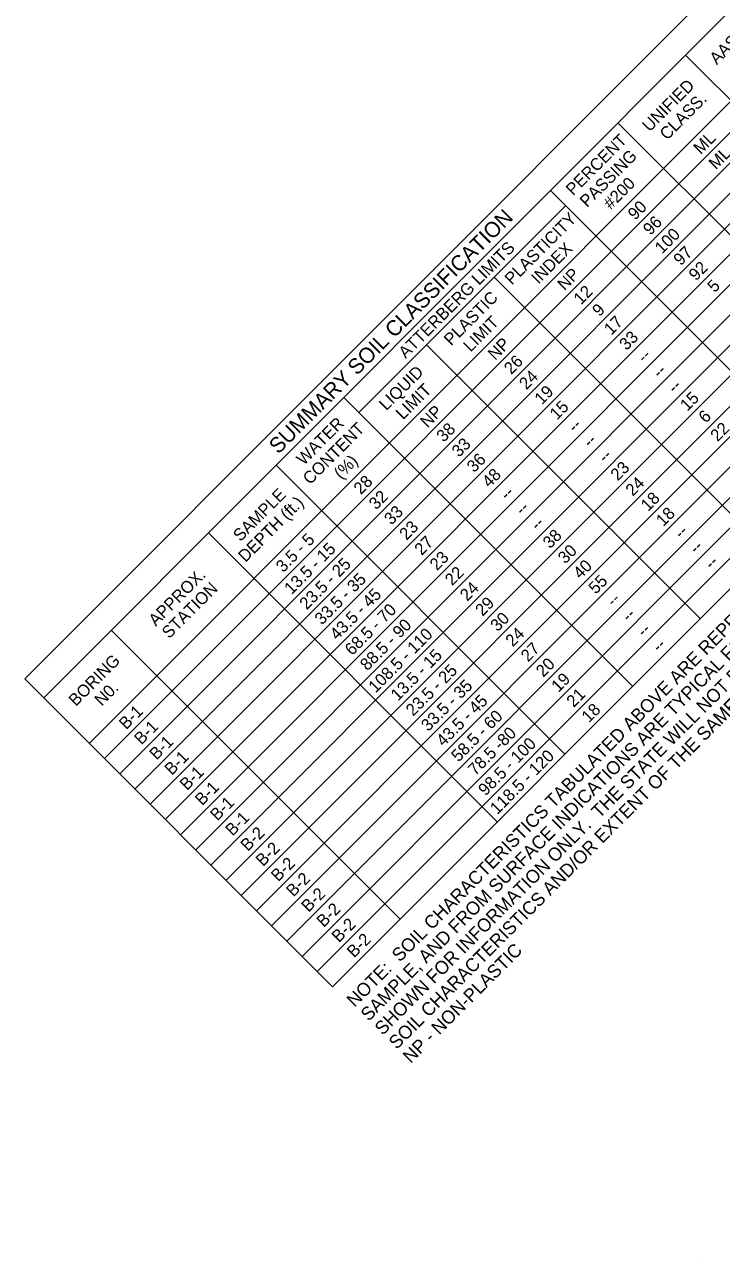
# Model space of a CAD drawing. Extents: x 1675667 to 1681231, y 227227 to 232694.
# Drawn here: x 1678206 to 1678522, y 230060 to 230621 of the extents above; entities that cross this region are included whole.
import ezdxf

# ---------------------------------------------------------------- set-up
doc = ezdxf.new("R2010")
doc.units = 0
doc.layers.add('Default', color=7, linetype='Continuous')
doc.layers.add('R_Annotation', color=7, linetype='Continuous')

msp = doc.modelspace()

# ---------------------------------------------------------------- linework, layer by layer
at = {"layer": 'Default'}
for p, q in [((1678205.92, 230324.54), (1678527.85, 230646.54)), ((1678214.54, 230315.92), (1678536.47, 230637.93)), ((1678235.23, 230295.24), (1678557.15, 230617.25)), ((1678465.12, 230525.19), (1678557.15, 230617.25)), ((1678242.12, 230288.35), (1678564.05, 230610.35)), ((1678636.8, 230476.27), (1678505.79, 230607.24)), ((1678249.02, 230281.46), (1678570.94, 230603.46)), ((1678255.91, 230274.56), (1678577.84, 230596.56)), ((1678262.81, 230267.67), (1678584.73, 230589.67)), ((1678269.7, 230260.77), (1678591.63, 230582.78)), ((1678276.6, 230253.88), (1678598.52, 230575.88)), ((1678606.12, 230445.58), (1678475.11, 230576.56)), ((1678283.49, 230246.99), (1678605.42, 230568.99)), ((1678290.39, 230240.09), (1678612.31, 230562.1)), ((1678297.28, 230233.2), (1678619.21, 230555.2)), ((1678304.18, 230226.31), (1678626.1, 230548.31)), ((1678575.45, 230414.9), (1678444.44, 230545.88)), ((1678311.07, 230219.41), (1678633, 230541.42)), ((1678357.58, 230445.21), (1678451.33, 230538.98)), ((1678317.97, 230212.52), (1678639.89, 230534.52)), ((1678324.86, 230205.63), (1678646.79, 230527.63)), ((1678331.76, 230198.73), (1678653.68, 230520.74)), ((1678338.65, 230191.84), (1678660.58, 230513.84)), ((1678345.55, 230184.95), (1678667.47, 230506.95)), ((1678543.05, 230382.49), (1678418.93, 230506.57)), ((1678512.37, 230351.81), (1678388.26, 230475.89)), ((1678481.69, 230321.13), (1678350.69, 230452.1)), ((1678451.02, 230290.44), (1678320.01, 230421.42)), ((1678420.34, 230259.76), (1678289.34, 230390.73)), ((1678376.22, 230215.63), (1678245.22, 230346.61)), ((1678345.55, 230184.95), (1678205.92, 230324.54)), ((1678511.22, 230060.07), (1678511.22, 230060.07))]:
    msp.add_line(p, q, dxfattribs=at)
at = {"layer": 'R_Annotation'}
msp.add_line((1678205.92, 230324.54), (1678205.92, 230324.54), dxfattribs=at)

# ---------------------------------------------------------------- texts
at = {"layer": 'Default'}
for s, height, p in [('AASHTO', 5.5, (1678519.93, 230602.65)), ('UNIFIED', 5.5, (1678489.45, 230572.16)), ('CLASS.', 5.5, (1678497.36, 230568.4)), ('PERCENT', 5.5, (1678454.75, 230543.28)), ('ML', 5.5, (1678512.65, 230561.95)), ('PASSING', 5.5, (1678461.08, 230537.95)), ('ML', 5.5, (1678519.54, 230555.05)), ('#200', 5.5, (1678471.8, 230537)), ('90', 5.5, (1678482.86, 230532.15)), ('SUMMARY SOIL CLASSIFICATION', 7, (1678320.99, 230426.07)), ('PLASTICITY', 5.5, (1678426.97, 230502.77)), ('96', 5.5, (1678489.77, 230525.27)), ('100', 5.5, (1678495.09, 230516.81)), ('ATTERBERG LIMITS', 5.5, (1678378.78, 230469.42)), ('INDEX', 5.5, (1678439, 230503.13)), ('97', 5.5, (1678503.58, 230511.5)), ('NP', 5.5, (1678450.89, 230500.18)), ('92', 5.5, (1678510.5, 230504.64)), ('5', 5.5, (1678518.96, 230499.31)), ('PLASTIC', 5.5, (1678399.4, 230475.2)), ('12', 5.5, (1678458.28, 230493.77)), ('9', 5.5, (1678466.71, 230488.42)), ('LIMIT', 5.5, (1678408.25, 230472.37)), ('17', 5.5, (1678472.04, 230479.96)), ('NP', 5.5, (1678419.36, 230468.63)), ('33', 5.5, (1678478.98, 230473.11)), ('26', 5.5, (1678426.69, 230462.18)), ('--', 5.5, (1678487.02, 230467.36)), ('LIQUID', 5.5, (1678369.99, 230445.78)), ('--', 5.5, (1678493.91, 230460.46)), ('NOTE:  SOIL CHARACTERISTICS TABULATED ABOVE ARE REPRESENTATIVE AT THE LOCATION OF THE', 6, (1678355.62, 230175.36)), ('24', 5.5, (1678433.55, 230455.25)), ('SAMPLE, AND FROM SURFACE INDICATIONS ARE TYPICAL FOR THE LIMITS SHOWN.  THESE DATA ARE ', 6, (1678361.99, 230169)), ('LIMIT', 5.5, (1678377.57, 230441.69)), ('19', 5.5, (1678440.52, 230448.43)), ('--', 5.5, (1678500.81, 230453.57)), ('15', 5.5, (1678506.55, 230445.53)), ('15', 5.5, (1678447.43, 230441.56)), ('SHOWN FOR INFORMATION ONLY.  THE STATE WILL NOT BE RESPONSIBLE FOR VARIATIONS IN THE ', 6, (1678368.35, 230162.64)), ('NP', 5.5, (1678388.68, 230437.95)), ('6', 5.5, (1678514.94, 230440.13)), ('WATER', 5.5, (1678332.51, 230421.01)), ('CONTENT', 5.5, (1678335.4, 230412.23)), ('SOIL CHARACTERISTICS AND/OR EXTENT OF THE SAME DIFFERING FROM THE ABOVE TABULATIONS.', 6, (1678374.72, 230156.27)), ('38', 5.5, (1678396.02, 230431.5)), ('--', 5.5, (1678455.48, 230435.81)), ('22', 5.5, (1678520.33, 230431.73)), ('33', 5.5, (1678402.98, 230424.67)), ('--', 5.5, (1678462.37, 230428.92)), ('36', 5.5, (1678409.81, 230417.71)), ('--', 5.5, (1678469.27, 230422.03)), ('(%)', 5.5, (1678349.49, 230414.66)), ('23', 5.5, (1678475.02, 230413.99)), ('28', 5.5, (1678358.45, 230407.71)), ('48', 5.5, (1678416.71, 230410.82)), ('24', 5.5, (1678481.82, 230407)), ('SAMPLE', 5.5, (1678303.78, 230386.44)), ('32', 5.5, (1678365.39, 230400.86)), ('--', 5.5, (1678424.8, 230405.13)), ('DEPTH (ft.)', 5.5, (1678306.08, 230377.07)), ('18', 5.5, (1678488.75, 230400.14)), ('33', 5.5, (1678372.3, 230393.98)), ('--', 5.5, (1678431.7, 230398.24)), ('18', 5.5, (1678495.65, 230393.25)), ('23', 5.5, (1678379.19, 230387.09)), ('--', 5.5, (1678438.59, 230391.34)), ('--', 5.5, (1678503.75, 230387.56)), ('3.5 - 5', 5.5, (1678323.18, 230372.43)), ('27', 5.5, (1678386.04, 230380.15)), ('38', 5.5, (1678444.29, 230383.25)), ('13.5 - 15', 5.5, (1678326.97, 230362.43)), ('23', 5.5, (1678392.99, 230373.3)), ('30', 5.5, (1678451.16, 230376.33)), ('--', 5.5, (1678510.64, 230380.67)), ('23.5 - 25', 5.5, (1678333.87, 230355.54)), ('40', 5.5, (1678458.06, 230369.44)), ('--', 5.5, (1678517.54, 230373.77)), ('APPROX.', 5.5, (1678265.41, 230348.07)), ('33.5 - 35', 5.5, (1678340.76, 230348.65)), ('22', 5.5, (1678399.86, 230366.39)), ('55', 5.5, (1678465.02, 230362.62)), ('STATION', 5.5, (1678271.45, 230342.43)), ('43.5 - 45', 5.5, (1678347.66, 230341.75)), ('24', 5.5, (1678406.68, 230359.42)), ('29', 5.5, (1678413.64, 230352.59)), ('--', 5.5, (1678473.07, 230356.88)), ('68.5 - 70', 5.5, (1678354.48, 230334.79)), ('30', 5.5, (1678420.49, 230345.65)), ('--', 5.5, (1678479.97, 230349.98)), ('88.5 - 90', 5.5, (1678361.37, 230327.89)), ('24', 5.5, (1678427.36, 230338.74)), ('--', 5.5, (1678486.86, 230343.09)), ('108.5 - 110', 5.5, (1678365.16, 230317.89)), ('13.5 - 15', 5.5, (1678375.24, 230314.18)), ('27', 5.5, (1678434.31, 230331.9)), ('--', 5.5, (1678493.76, 230336.2)), ('BORING', 5.5, (1678229.14, 230311.78)), ('23.5 - 25', 5.5, (1678382.13, 230307.29)), ('20', 5.5, (1678441.17, 230324.97)), ('19', 5.5, (1678448.12, 230318.12)), ('N0.', 5.5, (1678240.88, 230311.86)), ('33.5 - 35', 5.5, (1678389.03, 230300.39)), ('21', 5.5, (1678455.02, 230311.24)), ('43.5 - 45', 5.5, (1678395.92, 230293.5)), ('B-1', 5.5, (1678251.97, 230301.2)), ('58.5 - 60', 5.5, (1678402.74, 230286.53)), ('18', 5.5, (1678461.88, 230304.31)), ('B-1', 5.5, (1678258.86, 230294.31)), ('B-1', 5.5, (1678265.76, 230287.41)), ('78.5 -80', 5.5, (1678410.33, 230280.33)), ('98.5 - 100', 5.5, (1678414.98, 230271.19)), ('118.5 - 120', 5.5, (1678420.33, 230262.75)), ('B-1', 5.5, (1678272.65, 230280.52)), ('B-1', 5.5, (1678279.55, 230273.63)), ('B-1', 5.5, (1678286.44, 230266.73)), ('B-1', 5.5, (1678293.34, 230259.84)), ('B-1', 5.5, (1678300.23, 230252.95)), ('B-2', 5.5, (1678307.13, 230246.06)), ('B-2', 5.5, (1678314.03, 230239.16)), ('B-2', 5.5, (1678320.92, 230232.27)), ('B-2', 5.5, (1678327.82, 230225.38)), ('B-2', 5.5, (1678334.71, 230218.48)), ('B-2', 5.5, (1678341.61, 230211.59)), ('B-2', 5.5, (1678348.5, 230204.7)), ('B-2', 5.5, (1678355.4, 230197.8)), ('NP - NON-PLASTIC', 6, (1678381.08, 230149.91))]:
    msp.add_text(s, height=height, rotation=45.007, dxfattribs=at).set_placement(p)

doc.saveas('drawing.dxf')
